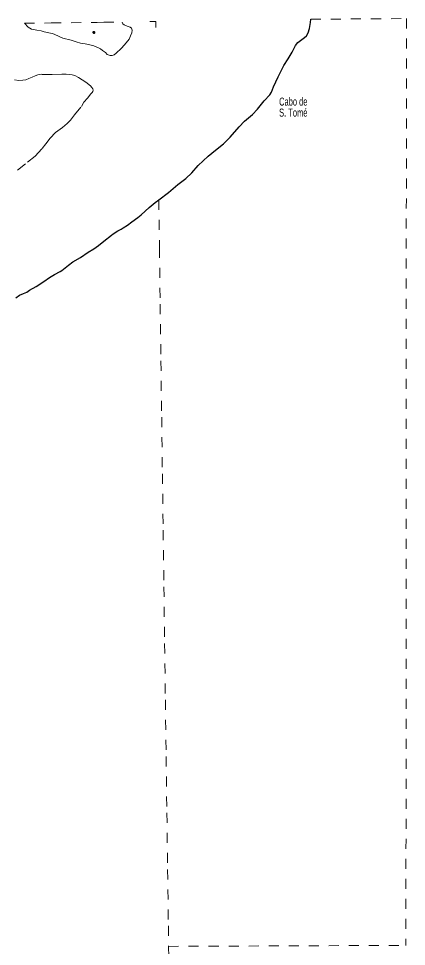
# Model space of a CAD drawing. Extents: x 267.7 to 296, y 7537.7 to 7565.8.
# Drawn here: x 292.14 to 296.02, y 7556.55 to 7565.82 of the extents above; entities that cross this region are included whole.
import ezdxf

# ---------------------------------------------------------------- set-up
doc = ezdxf.new("R2010")
doc.units = 0
doc.header["$LTSCALE"] = 0.04
doc.header["$PDMODE"] = 32
doc.header["$PDSIZE"] = 0.02
doc.linetypes.add('SHORT_DASHED', pattern=[2.7, 1.5, -1.2])
for name, color, linetype, lineweight in [('2', 7, 'Continuous', 25), ('21', 7, 'SHORT_DASHED', 13), ('62', 7, 'SHORT_DASHED', 13), ('63', 7, 'Continuous', 13)]:
    doc.layers.add(name, color=color, linetype=linetype, lineweight=lineweight)
doc.layers.add('61', color=7, linetype='Continuous')

msp = doc.modelspace()

# ---------------------------------------------------------------- linework, layer by layer
at = {"layer": '2'}
for points in [[(293.5427, 7564.0081), (293.6406, 7564.0846), (293.7332, 7564.1641), (293.8139, 7564.2234), (293.8708, 7564.2792), (293.9373, 7564.3516), (294.0358, 7564.4453), (294.1081, 7564.5046), (294.19, 7564.5687), (294.2541, 7564.6363), (294.3443, 7564.7384), (294.4, 7564.7953), (294.4771, 7564.8641), (294.5282, 7564.9164), (294.5946, 7564.9982), (294.6516, 7565.0587), (294.6694, 7565.0872), (294.6884, 7565.1382), (294.7334, 7565.2379), (294.7904, 7565.353), (294.8331, 7565.4194), (294.8758, 7565.4859), (294.9079, 7565.5512), (294.9316, 7565.582), (294.9565, 7565.601), (294.9969, 7565.6318), (295.0182, 7565.6485), (295.036, 7565.6793), (295.0467, 7565.7232), (295.0562, 7565.7825), (295.0621, 7565.8146)], [(292.5006, 7563.262), (292.558, 7563.2919), (292.5738, 7563.3047), (292.6411, 7563.3568), (292.6849, 7563.3896), (292.7598, 7563.4329), (292.8359, 7563.485), (292.8927, 7563.5213), (292.9413, 7563.5529), (292.9928, 7563.5956), (293.07, 7563.6564), (293.0881, 7563.6711), (293.132, 7563.6997), (293.166, 7563.7167), (293.1876, 7563.7296), (293.2298, 7563.7565), (293.2725, 7563.7899), (293.3316, 7563.8326), (293.3667, 7563.8595), (293.4474, 7563.9321), (293.5054, 7563.9824), (293.5427, 7564.0081)], [(292.2232, 7563.087), (292.2507, 7563.1058), (292.3163, 7563.145), (292.3941, 7563.1924), (292.4491, 7563.2322), (292.5006, 7563.262)], [(292.1132, 7563.0303), (292.1507, 7563.0554), (292.1905, 7563.0742), (292.2232, 7563.087)]]:
    msp.add_lwpolyline(points, dxfattribs=at)
at = {"layer": '21'}
for points in [[(292.2022, 7565.774), (292.2374, 7565.7343), (292.2717, 7565.7151), (292.3226, 7565.7069), (292.3666, 7565.6986), (292.3982, 7565.6876), (292.4779, 7565.6711), (292.4971, 7565.667), (292.5466, 7565.6436), (292.5837, 7565.6244), (292.6661, 7565.6052), (292.7184, 7565.5887), (292.7596, 7565.5763), (292.8063, 7565.5681), (292.853, 7565.5598), (292.8942, 7565.5474), (292.9396, 7565.5296), (292.9588, 7565.5186), (292.9808, 7565.5021), (293.0083, 7565.4815), (293.0275, 7565.4622), (293.055, 7565.454), (293.077, 7565.454), (293.0962, 7565.4581), (293.1169, 7565.4746), (293.1663, 7565.5213), (293.1993, 7565.5598), (293.2447, 7565.6162), (293.2611, 7565.6478), (293.2721, 7565.6794), (293.2763, 7565.7055), (293.2694, 7565.7247), (293.257, 7565.7371), (293.2378, 7565.7426), (293.2089, 7565.7522), (293.1966, 7565.7577), (293.1842, 7565.7673), (293.1759, 7565.7867)], [(292.1323, 7564.3065), (292.2317, 7564.3865), (292.3071, 7564.4471), (292.3769, 7564.5225), (292.4146, 7564.5682), (292.458, 7564.6265), (292.5106, 7564.6825), (292.5803, 7564.7339), (292.626, 7564.7728), (292.6603, 7564.8059), (292.7003, 7564.8608), (292.77, 7564.9442), (292.7951, 7564.9865), (292.8294, 7565.0265), (292.8626, 7565.0688), (292.8763, 7565.0836), (292.8843, 7565.0939), (292.8866, 7565.1065), (292.882, 7565.1191), (292.874, 7565.1316), (292.8603, 7565.1476), (292.8134, 7565.1853), (292.7403, 7565.2322), (292.7037, 7565.2516), (292.6763, 7565.2608), (292.618, 7565.2642), (292.5746, 7565.2653), (292.4786, 7565.263), (292.3723, 7565.2642), (292.3346, 7565.2585), (292.3071, 7565.2505), (292.2786, 7565.2345), (292.2454, 7565.2219), (292.2134, 7565.2093), (292.1837, 7565.2059), (292.1426, 7565.2036), (292.1003, 7565.2082)]]:
    msp.add_lwpolyline(points, dxfattribs=at)
msp.add_point((292.8939, 7565.6828), dxfattribs=at)
at = {"layer": '62'}
msp.add_line((293.6405, 7556.5476), (296.0113, 7556.5572), dxfattribs=at)
for points in [[(292.2022, 7565.774), (292.4656, 7565.7774), (292.9257, 7565.7834), (292.9925, 7565.7843), (293.1759, 7565.7867)], [(295.0621, 7565.8146), (296.0161, 7565.8217), (296.0113, 7556.5572)], [(293.5427, 7564.0081), (293.5489, 7563.5313), (293.5563, 7562.9663), (293.5637, 7562.4013), (293.5711, 7561.8364), (293.5785, 7561.2714), (293.5859, 7560.7064), (293.5933, 7560.1414), (293.6008, 7559.5764), (293.6082, 7559.0114), (293.6156, 7558.4464), (293.623, 7557.8814), (293.6304, 7557.3165), (293.6378, 7556.7515), (293.6405, 7556.5476)], [(293.6405, 7556.5476), (293.6452, 7556.1865), (293.6527, 7555.6215), (293.6601, 7555.0565), (293.6675, 7554.4915), (293.6749, 7553.9265), (293.6823, 7553.3615), (293.6898, 7552.7965), (293.6972, 7552.2316), (293.7046, 7551.6666)]]:
    msp.add_lwpolyline(points, dxfattribs=at)
at = {"layer": '63'}
msp.add_lwpolyline([(293.5126, 7565.7317), (293.5126, 7565.7933), (293.4519, 7565.7933)], dxfattribs=at)

# ---------------------------------------------------------------- texts
at = {"layer": '61', "width": 0.7}
for s, p in [('Cabo de', (294.7443, 7564.9517)), ('S. Tomé', (294.7443, 7564.8417))]:
    msp.add_text(s, height=0.08, dxfattribs=at).set_placement(p)

doc.saveas('drawing.dxf')
